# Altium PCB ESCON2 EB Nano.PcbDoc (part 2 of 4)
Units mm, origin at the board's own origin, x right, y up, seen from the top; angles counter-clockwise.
Board outline 67 x 70 mm, 6 copper layers (Top Side, Mid Layer 1, Mid Layer 2, Mid Layer 5, Mid Layer 6, Bottom Side), stack 1.48 mm thick; 293 components, 114 nets, 848 pads, 2005 vias.
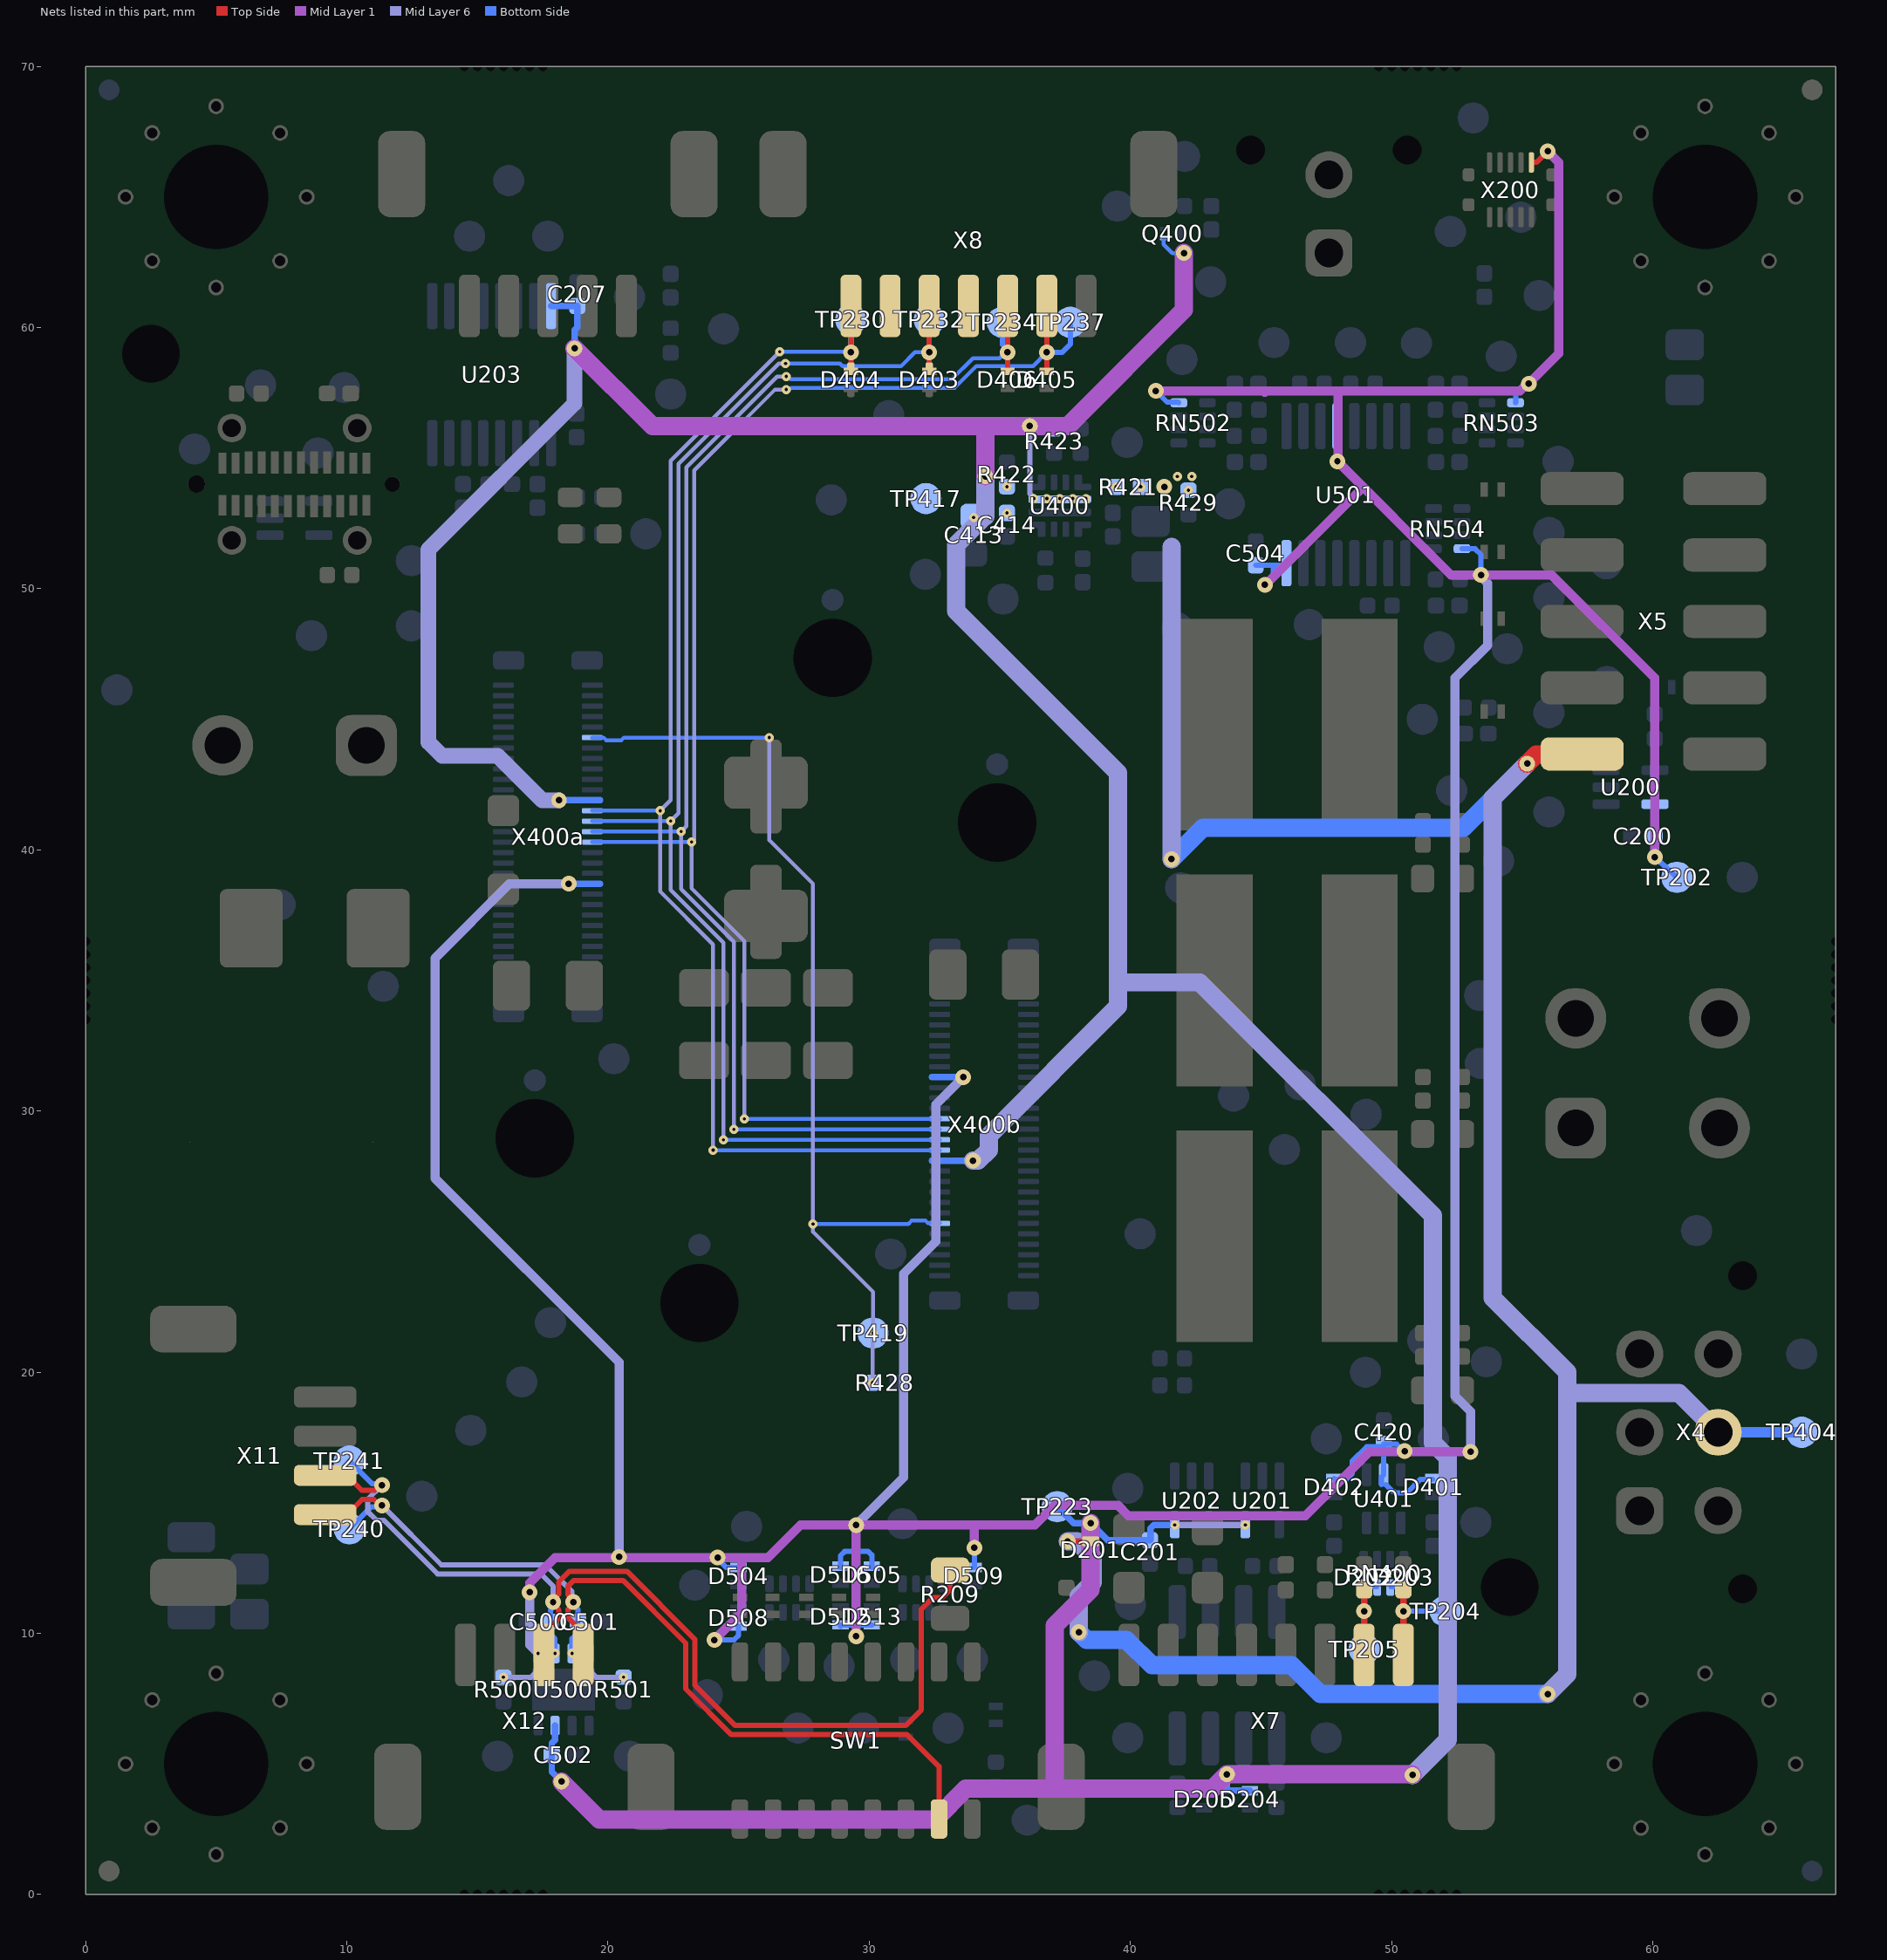
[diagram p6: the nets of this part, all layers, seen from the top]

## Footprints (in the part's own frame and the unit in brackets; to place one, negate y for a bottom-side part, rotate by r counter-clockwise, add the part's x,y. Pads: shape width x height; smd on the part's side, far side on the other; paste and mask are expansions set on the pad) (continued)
MTGNPH400A900V8H40_Snap-In_Spacer [mm] "Mounting Hole, Non-Plated; 9.00 mm Clearance, 4.00 mm Hole (with 8 vias), for 4mm Dia. Snap-In Spacer"
  round 0 hole 4 unplated mask+4.5: 1(0,0)
  round 0.6 hole 0.4: 2(0,3.47) 3(-2.45,2.45) 4(-3.47,0) 5(-2.45,-2.45) 6(0,-3.47) 7(2.45,-2.45) 8(3.47,0) 9(2.45,2.45)
  Multi-Layer region: -2.45,0 -4.5,0 -4.483,0.392 -4.432,0.781 -4.347,1.165 -4.229,1.539 -4.078,1.902 -3.897,2.25 -3.686,2.581 -3.447,2.893 -3.182,3.182 -2.893,3.447 -2.581,3.686 -2.25,3.897 -1.902,4.078 -1.539,4.229 -1.165,4.347 -0.781,4.432 -0.392,4.483 0,4.5 0.392,4.483 0.781,4.432 1.165,4.347 1.539,4.229 1.902,4.078 2.25,3.897 2.581,3.686 2.893,3.447 3.182,3.182 3.447,2.893 3.686,2.581 3.897,2.25 4.078,1.902 4.229,1.539 4.347,1.165 4.432,0.781 4.483,0.392 4.5,0 4.483,-0.392 4.432,-0.781 4.347,-1.165 4.229,-1.539 4.078,-1.902 3.897,-2.25 3.686,-2.581 3.447,-2.893 3.182,-3.182 2.893,-3.447 2.581,-3.686 2.25,-3.897 1.902,-4.078 1.539,-4.229 1.165,-4.347 0.781,-4.432 0.392,-4.483 0,-4.5 -0.392,-4.483 -0.781,-4.432 -1.165,-4.347 -1.539,-4.229 -1.902,-4.078 -2.25,-3.897 -2.581,-3.686 -2.893,-3.447 -3.182,-3.182 -3.447,-2.893 -3.686,-2.581 -3.897,-2.25 -4.078,-1.902 -4.229,-1.539 -4.347,-1.165 -4.432,-0.781 -4.483,-0.392 -4.5,0 -2.45,0 -2.441,-0.213 -2.413,-0.425 -2.367,-0.634 -2.302,-0.838 -2.221,-1.035 -2.122,-1.225 -2.007,-1.405 -1.877,-1.575 -1.732,-1.732 -1.575,-1.877 -1.405,-2.007 -1.225,-2.122 -1.035,-2.221 -0.838,-2.302 -0.634,-2.367 -0.425,-2.413 -0.213,-2.441 0,-2.45 0.213,-2.441 0.425,-2.413 0.634,-2.367 0.838,-2.302 1.035,-2.221 1.225,-2.122 1.405,-2.007 1.575,-1.877 1.732,-1.732 1.877,-1.575 2.007,-1.405 2.122,-1.225 2.221,-1.035 2.302,-0.838 2.367,-0.634 2.413,-0.425 2.441,-0.213 2.45,0 2.441,0.213 2.413,0.425 2.367,0.634 2.302,0.838 2.221,1.035 2.122,1.225 2.007,1.405 1.877,1.575 1.732,1.732 1.575,1.877 1.405,2.007 1.225,2.122 1.035,2.221 0.838,2.302 0.634,2.367 0.425,2.413 0.213,2.441 0,2.45 -0.213,2.441 -0.425,2.413 -0.634,2.367 -0.838,2.302 -1.035,2.221 -1.225,2.122 -1.405,2.007 -1.575,1.877 -1.732,1.732 -1.877,1.575 -2.007,1.405 -2.122,1.225 -2.221,1.035 -2.302,0.838 -2.367,0.634 -2.413,0.425 -2.441,0.213 -2.45,0
PANASONIC_AXF5G6012 [mm] "0.40 mm pitch; 60 pin, 14.70 mm L X 3.00 mm W X 1.45 mm H body"
  rrect50% 0.7x1.2 smd: 0a(6.75,-1.5) 0a(6.75,1.5) 0b(-6.75,-1.5) 0b(-6.75,1.5)
  rrect50% 0.2x0.8 smd: 1(5.8,-1.7) 2(5.8,1.7) 3(5.4,-1.7) 4(5.4,1.7) 5(5,-1.7) 6(5,1.7) 7(4.6,-1.7) 8(4.6,1.7) 9(4.2,-1.7) 10(4.2,1.7) 11(3.8,-1.7) 12(3.8,1.7) 13(3.4,-1.7) 14(3.4,1.7) 15(3,-1.7) 16(3,1.7) 17(2.6,-1.7) 18(2.6,1.7) 19(2.2,-1.7) 20(2.2,1.7) 21(1.8,-1.7) 22(1.8,1.7) 23(1.4,-1.7) 24(1.4,1.7) 25(1,-1.7) 26(1,1.7) 27(0.6,-1.7) 28(0.6,1.7) 29(0.2,-1.7) 30(0.2,1.7) 31(-0.2,-1.7) 32(-0.2,1.7) 33(-0.6,-1.7) 34(-0.6,1.7) 35(-1,-1.7) 36(-1,1.7) 37(-1.4,-1.7) 38(-1.4,1.7) 39(-1.8,-1.7) 40(-1.8,1.7) 41(-2.2,-1.7) 42(-2.2,1.7) 43(-2.6,-1.7) 44(-2.6,1.7) 45(-3,-1.7) 46(-3,1.7) 47(-3.4,-1.7) 48(-3.4,1.7) 49(-3.8,-1.7) 50(-3.8,1.7) 51(-4.2,-1.7) 52(-4.2,1.7) 53(-4.6,-1.7) 54(-4.6,1.7) 55(-5,-1.7) 56(-5,1.7) 57(-5.4,-1.7) 58(-5.4,1.7) 59(-5.8,-1.7) 60(-5.8,1.7)
  body extent -7.35,-1.8 7.35,1.8, height 1.45
PANASONIC_AXT410124 [mm] "0.40 mm pitch; 10 pin, 3.90 mm L X 1.45 mm W X 1.24 mm H body"
  rrect50% 0.45x0.5 smd: 0(-1.6,-0.575) 0(-1.6,0.575) 0(1.6,-0.575) 0(1.6,0.575)
  rrect50% 0.2x0.77 smd: 1(-0.8,-1.045) 2(-0.8,1.045) 3(-0.4,-1.045) 4(-0.4,1.045) 5(0,-1.045) 6(0,1.045) 7(0.4,-1.045) 8(0.4,1.045) 9(0.8,-1.045) 10(0.8,1.045)
  Top Side keep-out region: -0.983,0.335 0.983,0.335 0.983,0.61 -0.983,0.61
  Top Side keep-out region: -0.983,-0.61 0.983,-0.61 0.983,-0.335 -0.983,-0.335
  body extent -1.95,-1.17 1.95,1.18, height 1.24
PANASONIC_D8_VIB [mm] "Capacitor, Aluminum Electrolytic; D8 Panasonic Vibration proof 6.60 mm L X 6.60 mm W X 8.30 mm H Body"
  rrect36% 2x3.2 smd: 1(-2.55,0) 2(2.55,0)
  rrect36% 3.6x1.2 smd: 1(-2.4,0) 2(2.4,0)
  body extent -3.65,-3.3 3.65,3.3, height 8
PANASONIC_F_VIB [mil] "Capacitor, Aluminum Electrolytic; F Panasonic Vibration proof 8.30 mm L X 8.30 mm W X 10.50 mm H Body"
  round 1 smd: 1(-137.8,0) 2(137.8,0)
  Top Side region: 206.69,39.37 214.37,37.65 220.81,33.11 225.03,26.46 226.37,18.7 226.38,18.7 226.38,-18.7 225.03,-26.46 220.81,-33.11 214.37,-37.65 206.69,-39.37 206.69,-39.37 143.7,-39.37 143.7,-79.72 142.72,-84.62 139.95,-88.77 135.8,-91.55 130.9,-92.52 130.9,-92.52 105.31,-92.52 100.42,-91.55 96.26,-88.77 93.49,-84.62 92.52,-79.72 92.52,-79.72 92.52,-39.37 69.88,-39.37 62.12,-38.02 55.47,-33.81 50.93,-27.37 49.21,-19.68 49.21,-19.68 49.21,19.69 50.93,27.37 55.47,33.81 62.12,38.02 69.88,39.37 69.88,39.37 92.52,39.37 92.52,79.72 93.49,84.62 96.26,88.77 100.42,91.55 105.31,92.52 105.31,92.52 130.9,92.52 135.8,91.55 139.95,88.77 142.72,84.62 143.7,79.72 143.7,79.72 143.7,39.37
  Top Side region: -206.69,-39.37 -214.38,-37.65 -220.82,-33.11 -225.03,-26.46 -226.38,-18.7 -226.38,-18.7 -226.38,18.7 -223.92,28.86 -216.72,36.42 -206.69,39.37 -206.69,39.37 -143.7,39.37 -143.7,79.72 -142.73,84.62 -139.95,88.77 -135.8,91.55 -130.91,92.52 -130.91,92.52 -105.31,92.52 -100.42,91.55 -96.27,88.77 -93.49,84.62 -92.52,79.72 -92.52,79.72 -92.52,39.37 -69.88,39.37 -62.12,38.02 -55.47,33.81 -50.94,27.37 -49.21,19.68 -49.21,19.69 -49.21,-19.68 -50.94,-27.37 -55.47,-33.81 -62.12,-38.02 -69.88,-39.37 -69.88,-39.37 -92.52,-39.37 -92.52,-79.72 -93.49,-84.62 -96.27,-88.77 -100.42,-91.55 -105.31,-92.52 -105.31,-92.52 -130.91,-92.52 -135.8,-91.55 -139.95,-88.77 -142.73,-84.62 -143.7,-79.72 -143.7,-79.72 -143.7,-39.37
  body extent -191,-163 191,163, height 413
QFN16P45_200X200X100L15X25N [mm] "Quad Flat No-Lead (QFN), 0.45 mm pitch; 16 pin, square, 4 pin X 4 pin, 2.00 mm L X 2.00 mm W X 1.00 mm H body"
  rrect50% 0.6x0.25 smd paste-1: 1(-0.9,-0.725) 4(0.9,-0.725) 7(0.9,0.725) 10(-0.9,0.725)
  rrect50% 0.3x0.6 smd paste-1: 1(-0.7,-0.9) 4(0.7,-0.9) 7(0.7,0.9) 10(-0.7,0.9)
  rrect50% 0.25x0.6 smd: 2(-0.225,-0.9) 3(0.225,-0.9) 8(0.225,0.9) 9(-0.225,0.9)
  rrect50% 2.4x0.3 smd paste-1.187: 5(0,-0.25) 6(0,0.25)
  body extent -1,-1 1,1, height 1
RESC100X52X40L22N [mm] "Resistor, Chip; 1.00 mm L X 0.525 mm W X 0.40 mm H body"
  rrect51% 0.59x0.62 smd: 1(-0.47,0) 2(0.47,0)
  body extent -0.55,-0.3 0.55,0.3, height 0.4
RESC160X82X65L30N [mm] "Resistor, Chip; 1.60 mm L X 0.825 mm W X 0.65 mm H body"
  rrect49% 0.89x1.06 smd: 1(-0.765,0) 2(0.765,0)
  body extent -0.9,-0.52 0.9,0.53, height 0.65
RESC200X125X84L35N [mm] "Resistor, Chip; 2.00 mm L X 1.25 mm W X 0.84 mm H body"
  rrect50% 0.96x1.47 smd: 1(-0.925,0) 2(0.925,0)
  body extent -1.1,-0.72 1.1,0.73, height 0.84
RESC320X160X90L47N [mm] "Resistor, Chip; 3.20 mm L X 1.60 mm W X 0.90 mm H body"
  rrect43% 1.15x1.82 smd: 1(-1.48,0) 2(1.48,0)
  body extent -1.7,-0.9 1.7,0.9, height 0.9
RESCAXS8P50_200X102X55L30X30N [mm] "Resistor, Chip Array, 2 Side Convex, 0.50 mm pitch; 8 pin, 2.00 mm L X 1.025 mm W X 0.55 mm H body"
  rrect53% 0.34x0.64 smd: 1(-0.77,-0.545) 4(0.77,-0.545) 5(0.77,0.545) 8(-0.77,0.545)
  rrect53% 0.3x0.64 smd: 2(-0.25,-0.545) 3(0.25,-0.545) 6(0.25,0.545) 7(-0.25,0.545)
  body extent -1.1,-0.63 1.1,0.63, height 0.55
SODFL359X170X143L65X95N [mm] "Diode, Small Outline Diode Flat Lead (SODFL); 2.70 mm L X 1.70 mm W X 1.43 mm H body"
  rrect42% 1.2x1.21 smd: 1(-1.505,0) 2(1.505,0)
  body extent -1.9,-0.95 1.9,0.95, height 1.43
SODFL_DIODFN2_102X60X60L25X50L [mm] "Diode, combined footprint for SOD923 and SOD882 (0402); 1.025 mm L X 0.60 mm W X 0.60 mm H body"
  rrect50% 0.48x0.279 smd: 1(-0.425,0) 2(0.425,0)
  rect 0.28x0.55 smd: 1(-0.325,0) 2(0.325,0)
  body extent -0.55,-0.35 0.55,0.35, height 0.6
SOIC8P127_490X599X175L83X41N [mm] "Small Outline IC (SOIC), 1.27 mm pitch; 8 pin, 4.90 mm L X 3.90 mm W X 1.75 mm H body"
  rrect52% 0.66x2.07 smd: 1(-1.905,-2.42) 2(-0.635,-2.42) 3(0.635,-2.42) 4(1.905,-2.42) 5(1.905,2.42) 6(0.635,2.42) 7(-0.635,2.42) 8(-1.905,2.42)
  body extent -2.5,-3.1 2.5,3.1, height 1.75
SOIC16P127_1139X671X151L61X41N [mm] "DIP8-SMD-Small, 1.27 mm pitch; 16 pin, 11.39 mm L X 4.50 mm W X 1.51 mm H Body"
  rrect50% 0.634x1.501 smd: 1(-4.445,-3.007) 2(-3.175,-3.007) 3(-1.905,-3.007) 4(-0.635,-3.007) 5(0.635,-3.007) 6(1.905,-3.007) 7(3.175,-3.007) 8(4.445,-3.007) 9(4.445,3.007) 10(3.175,3.007) 11(1.905,3.007) 12(0.635,3.007) 13(-0.635,3.007) 14(-1.905,3.007) 15(-3.175,3.007) 16(-4.445,3.007)
  body extent -5.69,-3.35 5.7,3.35, height 1.55
SON9P65_300X300X100L40X30T240X160N [mm] "Small Outline No-Lead (SON) with Thermal Tab, 0.65 mm pitch; 8 pin, 3.00 mm L X 3.00 mm W X 1.00 mm H Body"
  rrect50% 0.349x0.759 smd: 1(-0.975,-1.385) 2(-0.325,-1.385) 3(0.325,-1.385) 4(0.975,-1.385) 5(0.975,1.385) 6(0.325,1.385) 7(-0.325,1.385) 8(-0.975,1.385)
  rect 2.4x1.6 smd paste-2.4: 9(0,0)
  body extent -1.55,-1.6 1.55,1.6, height 1
SOP16P65_500X640X120L83X24N [mm] "Small Outline Pkg (SOP), 0.65 mm pitch; 16 pin, 5.00 mm L X 4.40 mm W X 1.20 mm H body"
  rrect51% 0.39x1.77 smd: 1(-2.275,-2.625) 2(-1.625,-2.625) 3(-0.975,-2.625) 4(-0.325,-2.625) 5(0.325,-2.625) 6(0.975,-2.625) 7(1.625,-2.625) 8(2.275,-2.625) 9(2.275,2.625) 10(1.625,2.625) 11(0.975,2.625) 12(0.325,2.625) 13(-0.325,2.625) 14(-0.975,2.625) 15(-1.625,2.625) 16(-2.275,2.625)
  body extent -2.55,-3.3 2.55,3.3, height 1.2
SOT23-5P65_210X110L28X20N [mm] "Small Outline Transistor (SOT23), 0.65 mm pitch; 5 pin, 2.025 mm L X 1.25 mm W X 1.10 mm H body"
  rrect49% 0.37x1.04 smd: 1(-0.65,-0.935) 2(0,-0.935) 3(0.65,-0.935) 4(0.65,0.935) 5(-0.65,0.935)
  body extent -1.12,-1.2 1.12,1.2, height 1.1
SOT23-6P65_210X110L27X20N [mm] "Small Outline Transistor (SOT23), 0.65 mm pitch; 6 pin, 2.00 mm L X 1.25 mm W X 1.10 mm H body"
  rrect49% 0.37x0.88 smd: 1(-0.65,-0.925) 2(0,-0.925) 3(0.65,-0.925) 4(0.65,0.925) 5(0,0.925) 6(-0.65,0.925)
  body extent -1.1,-1.1 1.1,1.1, height 1.1
Steg_400X90_7Hole [mm] "Steg; 4.00 mm L X 0.90 mm W, 7 Hole"
  round 0 hole 0.35 unplated mask+0.15: 0(-1.5,0) 0(-1,0) 0(-0.5,0) 0(0,0) 0(0.5,0) 0(1,0) 0(1.5,0)
  Keep-Out Layer lines w0.05: -1.95,0 cw(c-1.5,0) -1.5,0.45 1.5,0.45 cw(c1.5,0) 1.95,0
TESTPOINT_c120 [mm] "Test Point; 1 pin, 1.20 mm D X 0.00 mm H body"
  round 1.2 smd paste-2: 1(0,0)
  body extent -0.6,-0.6 0.6,0.6, height 0.01
TRXDFN3_101X61X53L25X15N [mm] "Transistor, Dual Flat No-Lead (DFN) 3 pins, 0.65 mm pitch; 1.013 mm L X 0.613 mm W X 0.53 mm H body"
  rect 0.28x0.17 smd: 1(-0.325,0.175) 2(-0.325,-0.175)
  rect 0.28x0.52 smd: 3(0.325,0)
  body extent -0.54,-0.34 0.54,0.34, height 0.53
WURTH_973100365 [mm] "WA-SNTI Plastic Spacer Stud, D=4.0mm, L=10mm, M3, SW=6"
  body extent -3,-3.46 3,3.46, height 10.01
WURTH_9774015243_NPTH [mm] "WA-SMST SMT Steel Spacer with internal Thread M2, L=1.5mm"
  round 0 hole 3 unplated paste-2539.97 mask+1.25: 0(0,0)
  round 0.85 smd paste-5 mask+0.102: 1(2.225,0)
  Multi-Layer lines w0.85: 2.225,-0.025 cw(c0,0) 0,2.225 cw(c0,0) 2.225,-0.025
  body extent -2.17,-2.16 2.17,2.16, height 1.5
WURTH_9774015943_NPTH [mm] "WA-SMST SMT Steel Spacer with through hole Ø2.25mm, L=1.5mm"
  round 0 hole 3 unplated paste-2539.97 mask+1.25: 0(0,0)
  round 0.85 smd paste-5 mask+0.102: 1(2.225,0)
  Multi-Layer lines w0.85: 2.225,-0.025 cw(c0,0) 0,2.225 cw(c0,0) 2.225,-0.025
  body extent -2.17,-2.16 2.17,2.16, height 1.5

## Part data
C200 C201 C203 C207 C208 C209 C210 C211 C212 C414 C420 C502 C504: library part CMP-000709-3, "100nF X7R >=16V 20%", Case=0402, Case (Metric)=1005, Dielectric=X7R, Manufacturer=X, Max Operating Temperature=125°C, Maximum Working Voltage=16V, Min Operating Temperature=-55°C, Part Number="Ceramic, 0402, 100nF, 20%, >{}16V, X7R, @, Soft Termination: N, -55°C to 125°C", Tolerance=20%
C202 C206 C415 C421: library part CMP-001306-1, "100nF X7R >=50V 20%", Case=0402, Case (Metric)=1005, Dielectric=X7R, Manufacturer=X, Max Operating Temperature=125°C, Maximum Working Voltage=50V, Min Operating Temperature=-55°C, Part Number="Ceramic, 0402, 100nF, 20%, >{}50V, X7R, @, Soft Termination: N, -55°C to 125°C", Tolerance=20%
C204 C205: library part CMP-000937-4, "10nF X7R >=630V 20%", Case=0805, Case (Metric)=2012, Dielectric=X7R, Dielectric Withstanding Voltage="> 850V 1sec", Manufacturer=Murata, Max Operating Temperature=125°C, Maximum Working Voltage=630V, Min Operating Temperature=-55°C, Tolerance=20%
C400: library part CMP-001857-2, "Polymer Hybrid Elco 47uF >=50V 20% D=8mm, H=10.8mm", Case="F, D{}8mm, H{}10.8mm", Max Operating Temperature=105°C, Maximum Working Voltage=50V, Min Operating Temperature=-55°C, Ripple Current=1.25A, Tolerance=20%
C401: library part CMP-001205-2, "Polymer Hybrid Elco 22uF >=63V 20% D=6.3mm, H=8.3mm", Case="D8, D{}6.3mm, H{}8mm", Manufacturer="Nippon Chemi-Con", Max Operating Temperature=105°C, Maximum Working Voltage=63V, Min Operating Temperature=-55°C, Ripple Current=1.5A, Tolerance=20%
C402 C403 C404: library part CMP-001930-1, "470pF C0G/NP0/X7R >=100V 20%", Case=0402, Case (Metric)=1005, Dielectric=C0G/NP0/X7R, Manufacturer=X, Max Operating Temperature=125°C, Maximum Working Voltage=100V, Min Operating Temperature=-55°C, Part Number="Ceramic, 0402, 470pF, 20%, >{}100V, C0G/NP0/X7R, @, Soft Termination: N, -55°C to 125°C", Tolerance=20%
C405 C406 C407: library part CMP-001931-1, "220pF C0G/NP0/X7R >=100V 20%", Case=0402, Case (Metric)=1005, Dielectric=C0G/NP0/X7R, Manufacturer=X, Max Operating Temperature=125°C, Maximum Working Voltage=100V, Min Operating Temperature=-55°C, Part Number="Ceramic, 0402, 220pF, 20%, >{}100V, C0G/NP0/X7R, @, Soft Termination: N, -55°C to 125°C", Tolerance=20%
C408 C409 C410 C411 C412: library part CMP-001034-2, "4.7uF X7R/X7S >=50V 20% >2.5uF@24V", Case=1206, Case (Metric)=3216, Dielectric=X7R/X7S, Manufacturer=X, Max Operating Temperature=125°C, Maximum Working Voltage=50V, Min Operating Temperature=-55°C, Part Number="Ceramic, 1206, 4.7µF, 20%, >{}50V, X7R/X7S, 2.5µF@24V, Soft Termination: Y, -55°C to 125°C", Tolerance=20%, U@Value=24V, Value@U=2.5µF
C413: library part CMP-001146-2, "1uF X7R >=35V 20% Soft Termination", Case=0603, Case (Metric)=1608, Dielectric=X7R, Manufacturer=X, Max Operating Temperature=125°C, Maximum Working Voltage=35V, Min Operating Temperature=-55°C, Part Number="Ceramic, 0603, 1µF, 20%, >{}35V, X7R, @, Soft Termination: Y, -55°C to 125°C", Tolerance=20%
C416: library part CMP-002059-1, "4.7uF X7R/X7S/X6S >=35V 20%", Case=0805, Case (Metric)=2012, Dielectric=X7R/X7S/X6S, Max Operating Temperature=105°C, Maximum Working Voltage=35V, Min Operating Temperature=-55°C, Part Number="Ceramic, 0805, 4.7µF, 20%, >{}35V, X7R/X7S/X6S, @, Soft Termination: N, -55°C to 105°C", Tolerance=20%
C417: library part CMP-000705-3, "1nF X7R >=50V 20%", Case=0402, Case (Metric)=1005, Dielectric=X7R, Manufacturer=X, Max Operating Temperature=125°C, Maximum Working Voltage=50V, Min Operating Temperature=-55°C, Part Number="Ceramic, 0402, 1nF, 20%, >{}50V, X7R, @, Soft Termination: N, -55°C to 125°C", Tolerance=20%
C418 C419 C500 C501 C509: library part CMP-000706-3, "22pF C0G/NP0 >=50V 10%", Case=0402, Case (Metric)=1005, Dielectric=C0G/NP0, Manufacturer=X, Max Operating Temperature=125°C, Maximum Working Voltage=50V, Min Operating Temperature=-55°C, Part Number="Ceramic, 0402, 22pF, 10%, >{}50V, C0G/NP0, @, Soft Termination: N, -55°C to 125°C", Tolerance=10%
C503 C505 C506 C507 C508: library part CMP-000726-3, "220pF C0G/NP0/X7R >=50V 10%", Case=0402, Case (Metric)=1005, Dielectric=C0G/NP0/X7R, Manufacturer=X, Max Operating Temperature=125°C, Maximum Working Voltage=50V, Min Operating Temperature=-55°C, Part Number="Ceramic, 0402, 220pF, 10%, >{}50V, C0G/NP0/X7R, @, Soft Termination: N, -55°C to 125°C", Tolerance=10%
D200 D500 D501 D502 D503: library part CMP-001106-5, "Transient Voltage Suppressor Diode, 12V V(RWM), Bidirectional, 100W, 1 Element, SOD-882/DFN1006", Breakdown Voltage=13V, Case="SOD-882; DFN1006", Manufacturer=Diodes, Max Operating Temperature=125°C, Min Operating Temperature=-40°C
D201 D204 D205 D401 D402 D504 D505 D508 D509 D512 D513 D516: library part CMP-000606-13, "Diode Switching, >=70V, >=150mA, SOD882/DFN1006/0402/SOD-923F", Case="SOD882 / DFN1006 / 0402 / SOD-923F", Manufacturer=MCC, Max Operating Temperature=125°C, Min Operating Temperature=-40°C, Reverse Voltage=70V, RMS Current=150mA
D202 D203 D209 D210: library part CMP-000066-17, "Transient Voltage Suppressor Diode, 30V V(RWM), Bidirectional, ESD, 1 Element, 0402", Breakdown Voltage=30V, Case=0402, Manufacturer=Panasonic, Max Operating Temperature=125°C, Min Operating Temperature=-55°C
D206 D207: library part CMP-000633-9, "Schottky Diode, >=90V, >=1A, SOD-123FL/SOD-123W", Case="Sub SMA; SOD-123FL", Manufacturer="Taiwan Semiconductor", Max Operating Temperature=150°C, Min Operating Temperature=-55°C, Reverse Voltage=90V, RMS Current=1A
D208: library part CMP-000635-10, "Transient Voltage Suppressor Diode, 4-Line, 5V V(RWM), Unidirectional, 30W, 4 Element , SOT353/SC-88A", Breakdown Voltage=6.8V, Case="SOT353; SC-88A; SOT323-5L", Clamping Voltage=12V, Manufacturer=Nexperia, Max Breakdown Voltage=7.14V, Max Junction Temperature=150°C, Min Breakdown Voltage=6.46V, Min Operating Temperature=-65°C
D400: library part CMP-001762-3, "Transient Voltage Suppressor Diode, 28V V(RWM), Unidirectional, 200W, 1 Element, SOD-123F", Breakdown Voltage=31.1V, Case=SOD-123F, Clamping Voltage=45.4V, Manufacturer=Littelfuse, Max Operating Temperature=150°C, Min Operating Temperature=-55°C
D403 D404: library part CMP-001885-5, "Transient Voltage Suppressor Diode, 5V V(RWM), Unidirectional, 1 Element, SOD882/DFN1006/0402/SOD-923F/SOD-923", Breakdown Voltage=6.2V, Case=SOD882/DFN1006/0402/SOD-923/SOD-923F, Max Junction Temperature=150°C, Max Operating Temperature=125°C, Min Operating Temperature=-40°C, Min Storage Temperature=-55°C
D405 D406 D506 D507 D510 D511 D514 D515 D517: library part CMP-001117-7, "Transient Voltage Suppressor Diode, 3.3V V(RWM), Bidirectional, 30W, 1 Element, SOD-882/DFN1006", Breakdown Voltage=4V, Case="SOD-882; DFN1006", Manufacturer=Nexperia, Max Operating Temperature=125°C, Min Operating Temperature=-40°C
DS200: library part CMP-000723-7, "Single Color Chip LED, red, 0603", Case=0603, Color(s)=Red, Manufacturer=Dialight, Max Operating Temperature=100°C, Min Operating Temperature=-40°C
DS201: library part CMP-000722-6, "Single Color Chip LED, green, 0603", Case=0603, Color(s)=Green, Manufacturer=Dialight, Max Operating Temperature=100°C, Min Operating Temperature=-40°C
F400: library part CMP-001761-3, "Electric Fuse, Very Fast Blow, 4A, 125VAC, 125VDC, 50A (IR), Clip Assembly", Case="0157 with Fuse Clip", Current Rating=4A, Manufacturer=Littelfuse, Max Operating Temperature=125°C, Maximum Working Voltage=125V, Min Operating Temperature=-55°C
FD200 FD201 FD202 FD203: library part CMP-000010-5, "Fiducial, Global, Round; 0.80 mm D, 1.60 mm Clearance"
L400 L401 L402: library part CMP-001760-3, "Inductor Semi-Shielded, 33uH, 20%, I_RMS>2.3A, I_Sat>2.6A, R<120mOhm, 3131 (8080 Metric), 8.0x8.0mm, Height <=4.2mm", Case=3131, Case (Metric)=8080, DC Resistance=0.377, Max Operating Temperature=125°C, Min Operating Temperature=-40°C, RMS Current=2.3A, Saturation Current=2.6A, Tolerance=20%
LS200: library part CMP-001088-3, "Layer Stair 8 Layer"
MH200 MH201 MH202 MH203: library part CMP-001801-1, "Mounting Hole, Non-Plated; 9.00 mm Clearance, 4.00 mm Hole (with 8 vias), for 4mm Dia. Snap-In Spacer"
MH204 MH205: library part CMP-001004-5, "Mounting Hole, Non-Plated; 0.00 mm Clearance, 2.20 mm Hole"
MP200 MP201 MP202 MP203: library part CMP-001759-4, "WA-SNTI Plastic Spacer Stud, D=4.0mm, L=10mm, M3, SW=6", Max Operating Temperature=110°C, Min Operating Temperature=-30°C
MP400 MP401: library part CMP-001787-2, "WA-SMST SMT Steel Spacer with internal Thread M2, L=1.5mm", Manufacturer=Wurth, Max Operating Temperature=150°C, Min Operating Temperature=-55°C
MP402 MP403: library part CMP-001785-2, "WA-SMST SMT Steel Spacer with through hole Ø 2.25mm, L=1.5mm", Manufacturer=Wurth, Max Operating Temperature=150°C, Min Operating Temperature=-55°C
Q200: library part CMP-001108-5, "N-Channel MOSFET, Self Protected, 36V, 0.5ohm, SO-8", Case="SO-8, SOIC-8, PG-DSO-8", Drain Source Voltage=36V, Manufacturer="ST Microelectronics", Max Operating Temperature=150°C, Min Operating Temperature=-55°C
Q400: library part CMP-001890-1, "N-Channel MOSFET, 30V, 470mOhm, 0402/DFN1006/Picostar", Case="PICOSTAR, 3-XDFN, X2-DFN1006-3, DFN1006B-3, DFN1006-3 0402, DFN1006", Drain Source Voltage=30V, Max Operating Temperature=150°C, Min Operating Temperature=-55°C
R200: library part CMP-000161-11, "47R 1% 62.5mW 100ppm", Case=0402, Case (Metric)=1050, Manufacturer=X, Max Junction Temperature=155°C, Maximum Overload Voltage=100V, Maximum Working Voltage=50V, Min Operating Temperature=-55°C, Part Number="Thick-Film, 0402, 47, 1%, 62.5mW@70°C, 50V, 100ppm, -55°C to 155°C", Power Rating=62.5mW, Power Rating Temperature=70°C, Temperature Coefficient=100ppm, Tolerance=1%
R202 R203: library part CMP-000197-11, "2.2k 1% 62.5mW 100ppm", Case=0402, Case (Metric)=1050, Manufacturer=X, Max Junction Temperature=155°C, Maximum Overload Voltage=100V, Maximum Working Voltage=50V, Min Operating Temperature=-55°C, Part Number="Thick-Film, 0402, 2.2k, 1%, 62.5mW@70°C, 50V, 100ppm, -55°C to 155°C", Power Rating=62.5mW, Power Rating Temperature=70°C, Temperature Coefficient=100ppm, Tolerance=1%
R204 R205 R418: library part CMP-000173-11, "220R 1% 62.5mW 100ppm", Case=0402, Case (Metric)=1050, Manufacturer=X, Max Junction Temperature=155°C, Maximum Overload Voltage=100V, Maximum Working Voltage=50V, Min Operating Temperature=-55°C, Part Number="Thick-Film, 0402, 220, 1%, 62.5mW@70°C, 50V, 100ppm, -55°C to 155°C", Power Rating=62.5mW, Power Rating Temperature=70°C, Temperature Coefficient=100ppm, Tolerance=1%
R206: library part CMP-000935-4, "2M 5% 250mW 200ppm >=500V", Case=1206, Case (Metric)=3216, Manufacturer=X, Max Junction Temperature=155°C, Maximum Overload Voltage=1kV, Maximum Working Voltage=500V, Min Operating Temperature=-55°C, Part Number="Thick-Film, 1206, 2M, 5%, 250mW@70°C, 500V, 200ppm, -55°C to 155°C", Power Rating=250mW, Power Rating Temperature=70°C, Temperature Coefficient=200ppm, Tolerance=5%
R207 R208: library part CMP-000206-11, "5.1k 1% 62.5mW 100ppm", Case=0402, Case (Metric)=1050, Manufacturer=X, Max Junction Temperature=155°C, Maximum Overload Voltage=100V, Maximum Working Voltage=50V, Min Operating Temperature=-55°C, Part Number="Thick-Film, 0402, 5.1k, 1%, 62.5mW@70°C, 50V, 100ppm, -55°C to 155°C", Power Rating=62.5mW, Power Rating Temperature=70°C, Temperature Coefficient=100ppm, Tolerance=1%
R209: library part CMP-000325-10, "120R 1% 125mW 100ppm", Case=0805, Case (Metric)=2012, Manufacturer=X, Max Junction Temperature=155°C, Maximum Overload Voltage=300V, Maximum Working Voltage=150V, Min Operating Temperature=-55°C, Part Number="Thick-Film, 0805, 120, 1%, 125mW@70°C, 150V, 100ppm, -55°C to 155°C", Power Rating=125mW, Power Rating Temperature=70°C, Temperature Coefficient=100ppm, Tolerance=1%
R210 R421 R500 R501 R507 R508 R509: library part CMP-000466-10, "0R Jumper", Case=0402, Case (Metric)=1050, Manufacturer=X, Max Junction Temperature=155°C, Maximum Overload Voltage=100V, Maximum Working Voltage=50V, Min Operating Temperature=-55°C, Part Number="Thick-Film, 0402, 0, -55°C to 155°C", RMS Current=1A
R211 R212: library part CMP-000185-11, "680R 1% 62.5mW 100ppm", Case=0402, Case (Metric)=1050, Manufacturer=X, Max Junction Temperature=155°C, Maximum Overload Voltage=100V, Maximum Working Voltage=50V, Min Operating Temperature=-55°C, Part Number="Thick-Film, 0402, 680, 1%, 62.5mW@70°C, 50V, 100ppm, -55°C to 155°C", Power Rating=62.5mW, Power Rating Temperature=70°C, Temperature Coefficient=100ppm, Tolerance=1%
R213 R214 R215 R428: library part CMP-000492-11, "10k 1% 62.5mW 100ppm", Case=0402, Case (Metric)=1050, Manufacturer=X, Max Junction Temperature=155°C, Maximum Overload Voltage=100V, Maximum Working Voltage=50V, Min Operating Temperature=-55°C, Part Number="Thick-Film, 0402, 10k, 1%, 62.5mW@70°C, 50V, 100ppm, -55°C to 155°C", Power Rating=62.5mW, Power Rating Temperature=70°C, Temperature Coefficient=100ppm, Tolerance=1%
R406 R407 R408: library part CMP-000258-11, "390R 1% 100mW 100ppm", Case=0603, Case (Metric)=1608, Manufacturer=X, Max Junction Temperature=155°C, Maximum Overload Voltage=150V, Maximum Working Voltage=75V, Min Operating Temperature=-55°C, Part Number="Thick-Film, 0603, 390, 1%, 100mW@70°C, 75V, 100ppm, -55°C to 155°C", Power Rating=100mW, Power Rating Temperature=70°C, Temperature Coefficient=100ppm, Tolerance=1%
R422: library part CMP-000221-11, "470k 1% 62.5mW 100ppm", Case=0402, Case (Metric)=1050, Manufacturer=X, Max Junction Temperature=155°C, Maximum Overload Voltage=100V, Maximum Working Voltage=50V, Min Operating Temperature=-55°C, Part Number="Thick-Film, 0402, 470k, 1%, 62.5mW@70°C, 50V, 100ppm, -55°C to 155°C", Power Rating=62.5mW, Power Rating Temperature=70°C, Temperature Coefficient=100ppm, Tolerance=1%
R423: library part CMP-001891-1, "100k 0.1% 62.5mW 100ppm", Case=0402, Case (Metric)=1050, Manufacturer=X, Max Junction Temperature=155°C, Maximum Overload Voltage=100V, Maximum Working Voltage=50V, Min Operating Temperature=-55°C, Part Number="Thin-Film, 0402, 100k, 0.1%, 62.5mW@70°C, 50V, 100ppm, -55°C to 155°C", Power Rating=62.5mW, Power Rating Temperature=70°C, Temperature Coefficient=100ppm, Tolerance=0.1%
R424: library part CMP-001674-2, "27k 0.1% 62.5mW 100ppm", Case=0402, Case (Metric)=1050, Manufacturer=X, Max Junction Temperature=155°C, Maximum Overload Voltage=100V, Maximum Working Voltage=50V, Min Operating Temperature=-55°C, Part Number="Thin-Film, 0402, 27k, 0.1%, 62.5mW@70°C, 50V, 100ppm, -55°C to 155°C", Power Rating=62.5mW, Power Rating Temperature=70°C, Temperature Coefficient=100ppm, Tolerance=0.1%
R425: library part CMP-000497-12, "16k 1% 62.5mW 100ppm", Case=0402, Case (Metric)=1050, Max Junction Temperature=155°C, Maximum Overload Voltage=100V, Maximum Working Voltage=50V, Min Operating Temperature=-55°C, Part Number="Thick-Film, 0402, 16k, 1%, 62.5mW@70°C, 50V, 100ppm, -55°C to 155°C", Power Rating=62.5mW, Power Rating Temperature=70°C, Temperature Coefficient=100ppm, Tolerance=1%
R427: library part CMP-000225-11, "1M 1% 62.5mW 100ppm", Case=0402, Case (Metric)=1050, Manufacturer=X, Max Junction Temperature=155°C, Maximum Overload Voltage=100V, Maximum Working Voltage=50V, Min Operating Temperature=-55°C, Part Number="Thick-Film, 0402, 1M, 1%, 62.5mW@70°C, 50V, 100ppm, -55°C to 155°C", Power Rating=62.5mW, Power Rating Temperature=70°C, Temperature Coefficient=100ppm, Tolerance=1%
R429: library part CMP-002057-1, "0R47 5% 62.5mW 1000ppm", Case=0402, Case (Metric)=1050, Manufacturer=X, Max Junction Temperature=155°C, Maximum Overload Voltage=100V, Maximum Working Voltage=50V, Min Operating Temperature=-55°C, Part Number="Thick-Film, 0402, 0.47, 5%, 62.5mW@70°C, 50V, 1000ppm, -55°C to 155°C", Power Rating=62.5mW, Power Rating Temperature=70°C, Temperature Coefficient=1000ppm, Tolerance=5%
R502 R503 R504 R505 R506 R510: library part CMP-000169-11, "150R 1% 62.5mW 100ppm", Case=0402, Case (Metric)=1050, Manufacturer=X, Max Junction Temperature=155°C, Maximum Overload Voltage=100V, Maximum Working Voltage=50V, Min Operating Temperature=-55°C, Part Number="Thick-Film, 0402, 150, 1%, 62.5mW@70°C, 50V, 100ppm, -55°C to 155°C", Power Rating=62.5mW, Power Rating Temperature=70°C, Temperature Coefficient=100ppm, Tolerance=1%
RN400: library part CMP-002278-5, "4x47k 5% 62.5mW 200ppm 50V", Case=4x0402, Case (Metric)=2010, Max Junction Temperature=125°C, Maximum Overload Voltage=100V, Maximum Working Voltage=50V, Min Operating Temperature=-55°C, Part Number="Thick-Film concave/convex, 4x0402, 47k, 5%, 62.5mW@70°C, 50V, 200ppm, -55°C to 125°C", Power Rating=62.5mW, Power Rating Temperature=70°C, Temperature Coefficient=200ppm, Tolerance=5%
RN500 RN501: library part CMP-000792-5, "4x10k 5% 62.5mW 200ppm", Case=4x0402, Case (Metric)=2010, Manufacturer=X, Max Junction Temperature=125°C, Maximum Overload Voltage=50V, Maximum Working Voltage=25V, Min Operating Temperature=-55°C, Part Number="Thick-Film Concave/Convex, 4x0402, 10k, 5%, 62.5mW@70°C, 25V, 200ppm, -55°C to 125°C", Power Rating=62.5mW, Power Rating Temperature=70°C, Temperature Coefficient=200ppm, Tolerance=5%
RN502 RN503 RN504: library part CMP-000784-5, "4x4.7k 5% 62.5mW 200ppm", Case=4x0402, Case (Metric)=2010, Manufacturer=X, Max Junction Temperature=125°C, Maximum Overload Voltage=50V, Maximum Working Voltage=25V, Min Operating Temperature=-55°C, Part Number="Thick-Film Concave/Convex, 4x0402, 4.7k, 5%, 62.5mW@70°C, 25V, 200ppm, -55°C to 125°C", Power Rating=62.5mW, Power Rating Temperature=70°C, Temperature Coefficient=200ppm, Tolerance=5%
STEG200 STEG201 STEG202 STEG203 STEG204 STEG205: library part CMP-000007-5, "Breakaway tabs; 4.00 mm L X 0.90 mm W, 7 Hole"
SW1: library part CMP-001031-3, "Slide Dip Switch, 8 Switches, 0.025A, 24VDC, SMD", Manufacturer=Diptronics, Max Operating Temperature=85°C, Min Operating Temperature=-40°C
SYM200: library part CMP-001233-2, "Barcode EMS; 5.0 x 5.0 mm"
SYM201 SYM202: library part CMP-000018-6, "ESD-Sign; 5.0 mm L X 4.5 mm W"
SYM203: library part CMP-001854-7, "PCB Marking; 12.0 x 6.0 mm"
TP200 TP201 TP202 TP203 TP204 TP205 TP206 TP207 TP208 TP209 TP211 TP212 TP213 TP214 TP215 TP216 TP217 TP218 TP219 TP220 TP221 TP222 TP223 TP224 TP225 TP226 TP227 TP228 TP229 TP230 TP232 TP234 TP235 TP236 TP237 TP238 TP239 TP240 TP241 TP242 TP243 TP244 TP245 TP246 TP247 TP248 TP249 TP250 TP251 TP252 TP253 TP254 TP255 TP256 TP257 TP258 TP259 TP260 TP261 TP262 TP263 TP264 TP265 TP266 TP267 TP268 TP269 TP270 TP400 TP401 TP402 TP403 TP404 TP405 TP406 TP407 TP408 TP409 TP410 TP411 TP412 TP413 TP414 TP415 TP416 TP417 TP418 TP419 TP420 TP421 TP422 TP423 TP424 TP425 TP426 TP427 TP428 TP430 TP431 TP432 TP433 TP434 TP435 TP436 TP437 TP438 TP439 TP440: library part CMP-000014-7, "Test Point; 1 pin, 1.20 mm D"
U200: library part CMP-001041-6, "Single buffer with Schmitt-Trigger inputs", Case="5-TSSOP, SC-70-5, SOT-353", Manufacturer="Texas Instruments", Max Operating Temperature=125°C, Max Storage Temperature=150°C, Max Supply Voltage=5.5V, Min Operating Temperature=-40°C, Min Storage Temperature=-65°C, Min Supply Voltage=1.65V
U201 U202: library part CMP-002037-1, "Single, 2-Input NAND Gate, 5V", Case="SC-88A , SC-70-5, SOT353-1", Max Operating Temperature=125°C, Max Supply Voltage=5.5V, Min Operating Temperature=-40°C, Min Supply Voltage=4.5V
U203: library part CMP-000646-4, "RS-232 Line Transceiver, Dual channel 120kbps , 5.0V, TSSOP16", Case=TSSOP16, Manufacturer="Texas instruments", Max Operating Temperature=85°C, Max Supply Voltage=5.5V, Min Operating Temperature=-40°C, Min Supply Voltage=4.5V
U400: library part CMP-001843-5, "eFuse, 2.7V - 23V, 28mOhm, True Reverse Current Blocking, Input Reverse Polarity Protection, QFN10, 2mm x 2mm, 0.45mm Pitch", Case="VQFN-HR (10)", Manufacturer=TI, Max Junction Temperature=125°C, Max Storage Temperature=150°C, Min Operating Temperature=-40°C, Min Storage Temperature=-65°C, Working Voltage=23V
U401: library part CMP-001140-2, "Dual, Schmitt Trigger, none inverting Buffer, 5V", Case=SC70-6, Manufacturer="Texas Instruments", Max Operating Temperature=125°C, Max Supply Voltage=5.5V, Min Operating Temperature=-40°C, Min Supply Voltage=1.65V
U500: library part CMP-000672-8, "High Speed CAN Transceiver, Single, 5V, HVSON-8", Case="SOT782-1, HVSON8", Manufacturer="NXP Semiconductors", Max Operating Temperature=150°C, Max Supply Voltage=5.5V, Min Operating Temperature=-40°C, Min Supply Voltage=4.5V
U501: library part CMP-001174-5, "Low-Voltage High-Speed Quadruple Differential Line Receiver With +/-15-kV IEC ESD 16-TSSOP -40 to 85°C", Case=TSSOP16, Manufacturer="Texas Instruments", Max Operating Temperature=85°C, Max Storage Temperature=150°C, Max Supply Voltage=3.6V, Min Operating Temperature=-40°C, Min Storage Temperature=-65°C, Min Supply Voltage=3V
X1: library part CMP-001018-6, "Mini-Fit Jr. Vertical Header, 4.20mm Pitch, Dual Row, 2 Circuits, without Snap-in Plastic Peg PCB Lock, Tin, Natural", Max Operating Temperature=105°C, Min Operating Temperature=-40°C, Operating Current=9A, Operating Voltage=600V
X3: library part CMP-001016-8, "Mini-Fit Jr. Vertical Header, 4.20mm Pitch, Dual Row, 4 Circuits, without Snap-in Plastic Peg PCB Lock, Tin, Natural", Max Operating Temperature=105°C, Min Operating Temperature=-40°C, Operating Current=9A, Operating Voltage=600V
X4: library part CMP-001098-6, "Micro-Fit 3.0 Vertical Header, 3.00mm Pitch, Dual Row, 6 Circuits, with PCB Polarizing Peg, Black", Manufacturer=Molex, Max Operating Temperature=105°C, Min Operating Temperature=-40°C, Operating Current=8.5A, Operating Voltage=600V
X5: library part CMP-001165-3, "Header, 2.54mm Pitch, Dual Row, SMT, Vertical, 10 Circuits", Manufacturer=Amphenol, Max Operating Temperature=125°C, Min Operating Temperature=-65°C, Operating Current=3A, Operating Voltage=500V
X7: library part CMP-001014-7, "1.50mm Pitch, CLIK-Mate PCB Receptacle, Single Row, Surface Mount, Tin Plating, Positive Lock, with Pick-and-Place Polyimide Tape, 8 Circuits, Beige", Manufacturer=Molex, Max Operating Temperature=105°C, Min Operating Temperature=-40°C, Operating Current=2A, Operating Voltage=100V
X8: library part CMP-001015-7, "1.50mm Pitch, CLIK-Mate PCB Receptacle, Single Row, Surface Mount, Tin Plating, Positive Lock, with Pick-and-Place Polyimide Tape, 7 Circuits, Beige", Manufacturer=Molex, Max Operating Temperature=105°C, Min Operating Temperature=-40°C, Operating Current=2A, Operating Voltage=100V
X10: library part CMP-001023-6, "1.50mm Pitch, CLIK-Mate PCB Receptacle, Single Row, Surface Mount, Tin Plating, Positive Lock, with Pick-and-Place Polyimide Tape, 5 Circuits, Beige", Manufacturer=Molex, Max Operating Temperature=105°C, Min Operating Temperature=-40°C, Operating Current=2A, Operating Voltage=100V
X11 X12: library part CMP-001170-6, "1.50mm Pitch, CLIK-Mate PCB Receptacle, Single Row, Surface Mount, Tin Plating, Positive Lock, with Pick-and-Place Polyimide Tape, 4 Circuits, Beige", Manufacturer=Molex, Max Operating Temperature=105°C, Min Operating Temperature=-40°C, Operating Current=2A, Operating Voltage=100V
X13: library part CMP-001110-9, "USB Type C, SHLD, 24poles, vertical", Manufacturer=GTC, Max Operating Temperature=85°C, Min Operating Temperature=-25°C
X16: library part CMP-001107-4, "Micro-Fit 3.0 Vertical Header, 3.00mm Pitch, Dual Row, 2 Circuits, with PCB Polarizing Peg, Black", Manufacturer=Molex, Max Operating Temperature=105°C, Min Operating Temperature=-40°C, Operating Current=8.5A, Operating Voltage=600V
X200: library part CMP-001083-11, "Board to Board Connector, 2*5 pole, SMD, 0.4mm pitch, 1.5mm stacking Height", Manufacturer=Panasonic, Max Operating Temperature=85°C, Min Operating Temperature=-55°C, Operating Current=300mA, Operating Voltage=60V
X400a X400b: library part CMP-001692-7, "Board to Board Connector, 2*30 pole, SMD, 0.4mm pitch, 1.5mm stacking Height", Manufacturer=Panasonic, Max Operating Temperature=85°C, Min Operating Temperature=-55°C, Operating Current=500mA, Operating Voltage=30V

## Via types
v1: diameter 0.35, hole 0.125, Top Side to Mid Layer 1, tented both sides, 1153 vias
v2: diameter 0.6, hole 0.25, Top Side to Bottom Side, 489 vias
v3: diameter 0.35, hole 0.125, Mid Layer 6 to Bottom Side, tented both sides, 363 vias

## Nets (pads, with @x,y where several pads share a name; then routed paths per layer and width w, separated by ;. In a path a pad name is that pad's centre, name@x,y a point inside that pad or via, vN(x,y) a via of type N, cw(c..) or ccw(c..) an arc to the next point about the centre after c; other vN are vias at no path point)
3V3: C200.2 C420.2 C504.1 D401.1 D402.1 D504.1 D505.1 D508.1 D509.1 D512.1 D513.1 D516.1 RN502.4 RN503.5 RN504.4 TP202.1 U200.5 U401.5 U500.5 U501.4 U501.16 X200.1 X400a.40 X400b.40 | length 218.5
  Top Side w0.2: X200.1@55.35,66.32 55.545,66.32 v2(55.975,66.75)
  Mid Layer 1 w0.35: v2(17,11.575) 17,11.925 17.975,12.9 v2(24.2,12.9) 25.125,12.9 ; v2(24.075,9.75) 25.125,10.8 25.125,12.9 ; v2(29.5,9.885) v2(29.5,14.15) ; v2(34.025,13.275) 34.025,14.1 34.075,14.15 ; v2(40.975,57.575) 45.2,57.575 ; v2@45.15,50.125 48.9,53.875 ; 45.15,57.525 45.2,57.575 ; v2(53.025,16.95) 49.153,16.95 46.703,14.5 39.925,14.5 39.525,14.9 37.1,14.9 36.35,14.15 34.075,14.15 ; v2(55.975,66.75) 56.4,66.325 56.4,59 v2(55.25,57.85) 55.195,57.85 54.92,57.575 47.947,57.575 ; v2(60.075,39.725) 60.075,46.575 56.125,50.525 v2(53.425,50.525) 52.275,50.525 v2(47.925,54.875) 47.947,54.897 47.947,57.575 ; 25.125,12.9 26.125,12.9 27.375,14.15 v2(29.5,14.15) ; v2(29.5,14.15) 34.075,14.15 ; 45.2,57.575 47.947,57.575
  Mid Layer 6 w0.35: v2(17,11.575) 17,9.56 v3(17.325,9.235) ; v2(18.5,38.7) 16.225,38.7 13.375,35.85 13.375,27.428 20.425,20.378 v2(20.425,12.925) ; v2(29.5,14.15) 31.325,15.975 31.325,23.775 32.55,25 32.55,30.25 v2(33.6,31.3) ; v2(53.025,16.95) 53.025,18.5 52.425,19.1 52.425,46.575 53.675,47.825 53.675,50.207 53.425,50.457 v2(53.425,50.525)
  Bottom Side w0.2: v2(24.075,9.75) 24.825,9.75 25,9.925 D508.1@25,10.275 ; v2(24.2,12.9) 24.2,12.85 24.525,12.525 D504.1@25,12.525 ; D512.1@28.9,10.325 29.5,10.325 ; D516.1@28.9,12.525 28.9,12.975 29.063,13.138 29.488,13.138 ; v2@29.5,9.935 29.5,10.325 ; v2(29.5,14.15) 29.488,14.138 29.488,13.138 ; D513.1@30.1,10.325 29.5,10.325 ; D505.1@30.1,12.525 D505.1@30.1,12.575 30.1,13 29.962,13.138 29.488,13.138 ; D509.1@34,12.525 34.025,12.55 v2(34.025,13.275) ; v2(40.975,57.575) 41.412,57.138 41.837,57.138 RN502.4@41.855,57.12 ; C504.1@44.8,50.9 45.465,50.9 ; v2(45.15,50.15) 45.465,50.465 45.465,50.9 ; U501.16@45.95,50.9 45.465,50.9 ; U501.16@45.95,51 U501.16@45.975,50.975 ; D402.1@47.8,15.925 47.825,15.9 48.275,15.9 48.5,16.125 48.5,16.6 49.05,17.15 49.7,17.15 U401.5@49.7,16.075 49.615,15.99 U401.5@49.615,15.69 ; v2(47.925,54.875) U501.4@47.925,56.225 ; C420.2@49.7,17.25 50.198,17.25 v2@50.398,17.05 ; U401.5@49.785,15.69 50.054,15.421 ; 50.104,15.421 50.15,15.375 50.581,15.375 51.106,15.9 D401.1@51.569,15.9 ; v2@50.398,16.95 v2@50.5,16.95 ; RN504.4@52.695,51.53 53.195,51.53 53.425,51.3 v2(53.425,50.525) ; RN503.5@54.745,57.12 54.748,57.123 54.748,57.473 54.963,57.688 54.98,57.688 55.142,57.85 v2(55.25,57.85) ; U200.5@60.075,41.75 C200.2@60.075,40.525 v2(60.075,39.725) TP202.1@60.925,38.95
  Bottom Side w0.25: v2(18.5,38.7) X400a.40@19.4,38.7 X400a.40@19.7,38.7 ; X400b.40@32.4,31.3 v2(33.6,31.3)
  other v2: 50.5,16.975
5V0: C201.2 C207.1 C413.2 C414.2 C502.2 D204.2 D205.2 Q400.1 R421.2 R422.1 R423.2 TP223.1 TP417.1 U201.5 U202.5 U203.16 U400.5 U500.3 X400a.24 X400b.24 | length 192
  Mid Layer 1 w0.7: v2(18.225,4.325) 19.675,2.875 32.525,2.875 33.7,4.05 37.1,4.05 ; v2(18.725,59.2) 21.7,56.225 34.45,56.225 ; v2(34.45,54.3) 34.45,56.225 ; v2(38.475,14.225) 38.475,11.675 37.1,10.3 37.1,4.05 ; v2(42.05,62.85) 42.05,60.675 37.6,56.225 v2(36.15,56.225) 34.45,56.225 ; v2(50.8,4.575) 50.775,4.6 v2(43.7,4.6) 43.15,4.05 37.1,4.05
  Mid Layer 6 w0.2: v2(36.15,56.225) 36.15,53.641 36.3,53.491 v3(36.3,53.45)
  Mid Layer 6 w0.25: v3(41.7,14.155) v3(44.4,14.155)
  Mid Layer 6 w0.6: v2(18.125,41.9) 17.482,41.9 15.782,43.6 13.65,43.6 13.125,44.125 13.125,51.5 18.725,57.1 v2(18.725,59.2)
  Mid Layer 6 w0.7: v2(33.975,28.1) 34.165,28.1 34.575,28.51 34.575,29.063 39.525,34.013 39.525,34.925 ; v2(34.45,54.3) 34.45,52.773 34.423,52.773 33.325,51.675 33.325,49.15 39.525,42.95 39.525,34.925 ; v2(50.8,4.575) 52.15,5.925 52.15,16.725 51.575,17.3 51.575,26 42.65,34.925 39.525,34.925
  Bottom Side w0.15: v2(36.15,56.225) 36.272,56.225 36.377,56.12 R423.2@37.075,56.12 ; Q400.1@41.34,63.415 41.33,63.425 Q400.1@41.275,63.425 41.275,63.175 41.6,62.85 v2(42.05,62.85)
  Bottom Side w0.25: U203.16@17.825,60.825 C207.1@18.825,60.825 18.825,60 18.725,59.9 v2(18.725,59.2) ; U500.3@17.975,6.465 17.975,5.925 17.85,5.8 C502.2@17.85,5.35 17.85,4.7 v2(18.225,4.325) ; v2(18.125,41.9) X400a.24@19.4,41.9 X400a.24@19.7,41.9 ; X400b.24@32.4,28.1 v2(33.975,28.1) ; TP223.1@37.2,14.85 37.825,14.225 v2(38.475,14.225) 39.135,13.565 C201.2@40.75,13.565 40.775,13.59 40.775,14.025 40.905,14.155 v3(41.7,14.155) ; D205.2@42.825,3.975 43.7,3.975 ; v2@43.7,4.75 v2(43.7,4.6) 43.7,3.975 ; D204.2@44.575,3.975 43.7,3.975
  other v3: 34,52.725 35.275,52.9 36.8,53.45 37.3,53.45 37.8,53.45 38.3,53.45 35.275,53.905 39.455,53.9
5V0_sensor1_2: D201.2 R421.1 R429.2 TP404.1 X4.5 X5.2 | length 100.7
  Top Side w0.25: v2(37.6,13.525) D201.2@38.475,13.525
  Top Side w0.7: v2(55.195,43.3) 55.545,43.65 57.275,43.65 X5.2@57.295,43.67
  Mid Layer 6 w0.7: v2(37.6,13.525) 37.95,13.525 38.55,12.925 38.55,11.95 38.025,11.425 v2(38.025,10.044) ; v2(41.575,39.65) 41.575,51.6 ; v2(55.195,43.3) 53.875,41.98 53.875,22.85 56.725,20 56.725,19.2 ; v2(55.975,7.675) 56.725,8.425 56.725,19.2 ; X4.5@62.5,17.7 61,19.2 56.725,19.2
  Bottom Side w0.4: X4.5@62.5,17.7 TP404.1@65.7,17.7
  Bottom Side w0.7: v2(38.025,10.044) 38.316,9.752 39.848,9.752 40.825,8.775 46.175,8.775 47.275,7.675 v2(55.975,7.675) ; v2(41.575,39.65) 42.775,40.85 52.745,40.85 v2(55.195,43.3)
  other v2: 41.3,53.9
  other v3: 42.225,53.77 40.395,53.9 41.8,54.3 42.35,54.3
ADC_CB_Ident: R428.2 TP419.1 X400a.12 X400b.12 | length 38.2
  Mid Layer 6 w0.15: v3(26.175,44.3) 26.175,40.375 27.85,38.7 v3(27.85,25.675) 27.85,25.375 30.15,23.075 v3(30.15,21.5) 30.13,21.48 v3(30.13,19.6)
  Bottom Side w0.15: X400a.12@19.407,44.293 X400a.12@19.4,44.3 19.835,44.3 19.935,44.2 20.517,44.2 20.617,44.3 v3(26.175,44.3) ; v3(27.85,25.675) 31.5,25.675 31.625,25.8 32.159,25.8 32.257,25.702 32.698,25.702 X400b.12@32.7,25.7
C_AnIN1+: D404.1 TP230.1 X8.1 X400a.26 X400b.26 | length 51.1
  Top Side w0.2: D404.1@29.3,58.325 v2(29.3,59.05) X8.1@29.3,60.825
  Mid Layer 6 w0.15: v3(24.025,28.5) 24.025,36.382 22,38.407 v3(22,41.5) 22.4,41.9 22.4,54.9 v3(26.575,59.075)
  Bottom Side w0.15: X400a.26@19.4,41.5 v3(22,41.5) ; v3(24.025,28.5) X400b.26@32.7,28.5 ; v3(26.575,59.075) 29.275,59.075 v2(29.3,59.05)
  Bottom Side w0.2: v2(29.3,59.05) TP230.1@29.3,60.3
C_AnIN1-: X8.2
C_AnIN2+: D403.1 TP232.1 X8.3 X400a.28 X400b.28 | length 53.3
  Top Side w0.2: D403.1@32.3,58.325 v2(32.3,59.05) X8.3@32.3,60.825
  Mid Layer 6 w0.15: v3(24.425,28.9) 24.425,36.445 22.4,38.47 v3(22.4,41.1) 22.7,41.4 22.7,54.776 26.542,58.618 26.793,58.618 v3(26.8,58.625)
  Bottom Side w0.15: X400a.28@19.4,41.1 v3(22.4,41.1) ; v3(24.425,28.9) X400b.28@32.7,28.9 ; v3(26.8,58.625) 28.875,58.625 28.975,58.525 31.225,58.525 31.75,59.05 v2(32.3,59.05)
  Bottom Side w0.2: v2(32.3,59.05) TP232.1@32.3,60.3
C_AnIN2-: X8.4
C_AnOUT1: D406.2 TP234.1 X8.5 X400a.30 X400b.30 | length 55.5
  Top Side w0.2: D406.2@35.3,58.325 v2(35.3,59.05) X8.5@35.3,60.825
  Mid Layer 6 w0.15: v3(24.825,29.3) 24.825,36.476 22.8,38.501 v3(22.8,40.7) 23,40.9 23,54.651 26.474,58.125 v3(26.825,58.125)
  Bottom Side w0.15: X400a.30@19.4,40.7 v3(22.8,40.7) ; v3(24.825,29.3) X400b.30@32.7,29.3 ; v3(26.825,58.125) 26.879,58.125 26.99,58.014 33.158,58.014 33.969,58.825 34.987,58.825 35.212,59.05 v2(35.3,59.05)
  Bottom Side w0.2: TP234.1@35.1,60.2 35.1,59.352 35.3,59.152 v2(35.3,59.05)
C_AnOUT2: D405.2 TP237.1 X8.6 X400a.32 X400b.32 | length 56.7
  Top Side w0.2: D405.2@36.8,58.325 v2(36.8,59.05) X8.6@36.8,60.825
  Mid Layer 6 w0.15: v3(25.225,29.7) 25.225,36.501 23.2,38.526 v3(23.2,40.3) 23.3,40.4 23.3,54.527 26.398,57.625 v3(26.825,57.625)
  Bottom Side w0.15: X400a.32@19.4,40.3 v3(23.2,40.3) ; v3(25.225,29.7) X400b.32@32.7,29.7 ; v3(26.825,57.625) 26.863,57.663 26.983,57.663 27.013,57.693 33.268,57.693 34.1,58.525 36.275,58.525 v2(36.8,59.05)
  Bottom Side w0.2: v2(36.8,59.05) 37.393,59.05 37.7,59.357 TP237.1@37.7,60.2
C_CANH: C501.1 R501.2 SW1.7 TP240.1 U500.7 X11.1 X12.1 | length 40.7
  Top Side w0.2: X11.1@9.175,14.55 10.015,14.55 10.593,15.128 11.038,15.128 11.242,14.925 v2@11.35,14.925 ; v2@18.65,11.092 18.475,10.917 18.475,10.59 19.05,10.015 X12.1@19.05,9.175 ; v2@18.65,11.308 18.475,11.483 18.475,11.81 18.69,12.025 20.575,12.025 22.975,9.625 22.975,7.875 24.725,6.125 31.45,6.125 32.675,4.9 SW1.7@32.675,2.893
  Mid Layer 6 w0.2: v2(11.35,14.9) 13.625,12.625 17.6,12.625 18.626,11.599 18.626,11.249 v2(18.675,11.2) ; v3(18.625,9.235) 19.54,8.32 v3(20.6,8.32)
  Bottom Side w0.2: TP240.1@10.1,14 10.951,14.851 11.301,14.851 v2(11.35,14.9) ; v3(18.625,9.235) 18.625,9.8 18.825,10 18.825,10.425 C501.1@18.85,10.45 18.85,10.917 18.675,11.092 v2(18.675,11.2)
C_CANL: C500.1 R209.2 R500.2 TP241.1 U500.6 X11.2 X12.2 | length 45.5
  Top Side w0.2: X11.2@9.175,16.025 10.025,16.025 10.568,15.482 11.073,15.482 11.267,15.675 v2(11.35,15.675) ; X12.2@17.575,9.175 17.575,10.025 18.125,10.575 18.125,10.892 v2@17.925,11.092 ; v2(17.9,11.2) v2@17.924,11.224 ; v2@17.925,11.308 18.125,11.508 18.125,11.975 18.525,12.375 20.725,12.375 23.325,9.775 23.325,8.02 24.87,6.475 31.4,6.475 32,7.075 32,10.924 32.451,11.375 32.8,11.375 33.1,11.675 R209.2@33.1,12.425
  Mid Layer 6 w0.2: v2@11.344,15.675 10.797,15.128 10.797,14.673 11.145,14.325 11.425,14.325 13.475,12.275 17.433,12.275 17.9,11.808 v2(17.9,11.2) ; v3(16,8.32) 17.06,8.32 v3(17.975,9.235)
  Bottom Side w0.2: TP241.1@10.1,16.6 10.963,15.737 11.288,15.737 v2(11.35,15.675) ; v2(17.9,11.2) 17.823,11.123 17.823,10.906 17.8,10.883 17.8,9.975 17.975,9.8 v3(17.975,9.235)
C_DigIN1: D203.2 RN400.5 RN400.6 TP204.1 X7.1 | length 5.5
  Top Side w0.25: X7.1@50.45,9.175 D203.2@50.45,11.665
  Bottom Side w0.15: RN400.6@49.95,11.755 RN400.5@50.47,11.755 50.47,10.87 v2(50.45,10.85)
  Bottom Side w0.2: v2(50.45,10.85) TP204.1@52.05,10.85
C_DigIN2: D202.2 RN400.7 RN400.8 TP205.1 X7.2 | length 5.4
  Top Side w0.25: X7.2@48.95,9.175 D202.2@48.95,11.665
  Bottom Side w0.15: v2(48.95,10.85) 48.93,10.87 RN400.8@48.93,11.755 RN400.7@49.45,11.755
  Bottom Side w0.2: TP205.1@48.95,9.4 v2(48.95,10.85)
